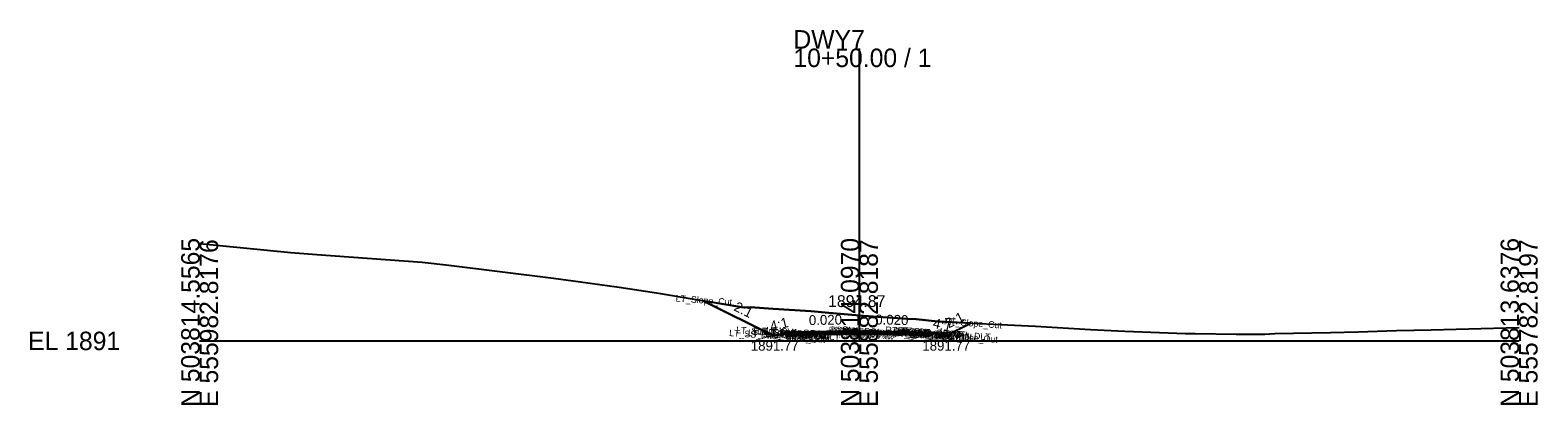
# Model space of a CAD drawing. Extents: x -26 to 1503, y -10 to 1052.
# Drawn here: x -25.7 to 202.8, y 490.3 to 547.1 of the extents above; entities that cross this region are included whole.
import ezdxf

# ---------------------------------------------------------------- set-up
doc = ezdxf.new("R2010")
doc.units = 0
for name, color, linetype in [('Default', 7, 'Continuous'), ('Exist Cross Section Cell', 7, 'Continuous'), ('Exist XS Center Line Elevation Label', 7, 'Continuous'), ('Exist XS Ground Line', 7, 'Continuous'), ('Prop CMT Pvmt Course 1', 7, 'Continuous'), ('Prop CMT Pvmt Course 2', 7, 'Continuous'), ('Prop CMT Pvmt Surface', 7, 'Continuous'), ('Prop CMT Shld Paved Course 1', 7, 'Continuous'), ('Prop CMT Shld Paved Course 2', 7, 'Continuous'), ('Prop CMT Slope Grass', 7, 'Continuous'), ('Prop CMT Subgrade Earthwork', 7, 'Continuous'), ('Prop XS Ditch Standard Text', 7, 'Continuous'), ('Prop XS Earthwork Shape', 7, 'Continuous'), ('Prop XS SE Text', 7, 'Continuous'), ('Prop XS Side Slope Text', 7, 'Continuous'), ('Typical Text Asphalt at Bridge Approach CELL', 7, 'Continuous')]:
    doc.layers.add(name, color=color, linetype=linetype)

msp = doc.modelspace()

# ---------------------------------------------------------------- linework, layer by layer
at = {"layer": 'Exist Cross Section Cell'}
for p, q in [((100, 500), (100, 544.31)), ((0, 500), (100, 500)), ((100, 500), (200, 500))]:
    msp.add_line(p, q, dxfattribs=at)
at = {"layer": 'Exist XS Ground Line'}
for p, q in [((0, 514.77), (13.84, 513.38)), ((13.84, 513.38), (17.75, 513.1)), ((17.75, 513.1), (33.75, 511.94)), ((33.75, 511.94), (37.75, 511.48)), ((37.75, 511.48), (53.66, 509.51)), ((53.66, 509.51), (57.75, 508.93)), ((57.75, 508.93), (63.59, 508.15)), ((63.59, 508.15), (69.27, 507.31)), ((69.27, 507.31), (81.58, 505.2)), ((81.58, 505.2), (82.11, 505.11)), ((82.11, 505.11), (82.77, 505.08)), ((82.77, 505.08), (83.42, 505.11)), ((83.42, 505.11), (86.91, 504.86)), ((86.91, 504.86), (92.65, 504.5)), ((92.65, 504.5), (94.81, 504.33)), ((94.81, 504.33), (100, 503.87)), ((100, 503.87), (100.58, 503.82)), ((100.58, 503.82), (107.27, 503.36)), ((107.27, 503.36), (108.59, 503.29)), ((108.59, 503.29), (111.9, 502.96)), ((111.9, 502.96), (126.71, 502.22)), ((126.71, 502.22), (135.04, 501.72)), ((135.04, 501.72), (140.23, 501.46)), ((140.23, 501.46), (149.43, 501.1)), ((149.43, 501.1), (150.9, 501.1)), ((150.9, 501.1), (157.12, 501.04)), ((157.12, 501.04), (161.46, 501.01)), ((161.46, 501.01), (162.96, 501.1)), ((162.96, 501.1), (171.41, 501.28)), ((171.41, 501.28), (175.59, 501.37)), ((175.59, 501.37), (181.4, 501.6)), ((181.4, 501.6), (186.65, 501.69)), ((186.65, 501.69), (198.05, 501.98)), ((198.05, 501.98), (200, 502.02))]:
    msp.add_line(p, q, dxfattribs=at)
at = {"layer": 'Prop CMT Pvmt Course 1'}
for points in [[(100, 501.55), (90, 501.35)], [(90, 501.35), (90, 501.1)], [(90, 501.1), (100, 501.3)], [(100, 501.3), (100, 501.55)], [(100, 501.55), (110, 501.35)], [(100, 501.3), (100, 501.55)], [(110, 501.1), (100, 501.3)], [(110, 501.35), (110, 501.1)]]:
    msp.add_lwpolyline(points, dxfattribs=at)
msp.add_lwpolyline([(100, 501.3), (100, 501.42), (100, 501.42), (100, 501.3)], close=True, dxfattribs=at)
msp.add_lwpolyline([(100, 501.3), (100, 501.42), (100, 501.42), (100, 501.3)], close=True, dxfattribs=at)
at = {"layer": 'Prop CMT Pvmt Course 2'}
for points in [[(100, 501.3), (90, 501.1)], [(90, 501.1), (90, 500.85)], [(90, 500.85), (100, 501.05)], [(100, 501.05), (100, 501.3)], [(100, 501.05), (100, 501.3)], [(100, 501.3), (110, 501.1)], [(110, 500.85), (100, 501.05)], [(110, 501.1), (110, 500.85)]]:
    msp.add_lwpolyline(points, dxfattribs=at)
at = {"layer": 'Prop CMT Pvmt Surface'}
for points in [[(100, 501.55), (90, 501.35)], [(100, 501.55), (110, 501.35)]]:
    msp.add_lwpolyline(points, dxfattribs=at)
at = {"layer": 'Prop CMT Shld Paved Course 1'}
for points in [[(90, 501.35), (89.74, 501.09)], [(89.74, 501.09), (90, 501.1)], [(90, 501.1), (90, 501.35)], [(110, 501.35), (110.26, 501.09)], [(110, 501.1), (110, 501.35)], [(110.26, 501.09), (110, 501.1)]]:
    msp.add_lwpolyline(points, dxfattribs=at)
at = {"layer": 'Prop CMT Shld Paved Course 2'}
for points in [[(90, 501.1), (89.74, 501.09), (89.24, 501.08), (89, 500.84)], [(89, 500.84), (90, 500.85)], [(90, 500.85), (90, 501.1)], [(110, 501.1), (110.26, 501.09), (110.76, 501.08), (111, 500.84)], [(110, 500.85), (110, 501.1)], [(111, 500.84), (110, 500.85)]]:
    msp.add_lwpolyline(points, dxfattribs=at)
at = {"layer": 'Prop CMT Slope Grass'}
for points in [[(90, 501.35), (89, 501.27), (87, 500.77), (76.33, 506.1)], [(110, 501.35), (111, 501.27), (113, 500.77), (116.89, 502.71)]]:
    msp.add_lwpolyline(points, dxfattribs=at)
at = {"layer": 'Prop CMT Subgrade Earthwork'}
for points in [[(90, 500.85), (89, 500.84), (88.66, 501.18)], [(100, 501.05), (90, 500.85)], [(100, 501.05), (110, 500.85)], [(110, 500.85), (111, 500.84), (111.34, 501.18)]]:
    msp.add_lwpolyline(points, dxfattribs=at)
at = {"layer": 'Prop XS Earthwork Shape'}
for points in [[(111, 501.27), (111.34, 501.18), (113, 500.77), (116.89, 502.71), (111.9, 502.96), (108.59, 503.29), (107.27, 503.36), (100.58, 503.82), (100, 503.87), (94.81, 504.33), (92.65, 504.5), (86.91, 504.86), (83.42, 505.11), (82.77, 505.08), (82.11, 505.11), (81.58, 505.2), (76.33, 506.1), (87, 500.77), (88.66, 501.18), (89, 501.27), (90, 501.35), (100, 501.55), (110, 501.35)], [(100, 501.05), (90, 500.85), (89, 500.84), (88.66, 501.18), (89, 501.27), (90, 501.35), (100, 501.55), (110, 501.35), (111, 501.27), (111.34, 501.18), (111, 500.84), (110, 500.85)]]:
    msp.add_lwpolyline(points, close=True, dxfattribs=at)

# ---------------------------------------------------------------- texts
at = {"layer": 'Default'}
msp.add_text('-', height=0.0001, dxfattribs=at).set_placement((0, 500))
at = {"layer": 'Exist Cross Section Cell'}
for s, p in [('DWY7', (90, 544.31)), ('10+50.00 / 1', (90, 541.51)), ('EL 1891', (-26, 498.6))]:
    msp.add_text(s, height=2.8, dxfattribs=at).set_placement(p)
for s, p in [('N 503814.5565', (0, 490)), ('E 555982.8176', (2.8, 490)), ('N 503814.0970', (100, 490)), ('E 555882.8187', (102.8, 490)), ('N 503813.6376', (200, 490)), ('E 555782.8197', (202.8, 490))]:
    msp.add_text(s, height=2.8, rotation=90, dxfattribs=at).set_placement(p)
at = {"layer": 'Exist XS Center Line Elevation Label'}
msp.add_text('1894.87', height=1.8, dxfattribs=at).set_placement((95.25, 505.13))
at = {"layer": 'Prop XS Ditch Standard Text'}
for p in [(83.54, 498.52), (109.54, 498.52)]:
    msp.add_text('1891.77', height=1.5, dxfattribs=at).set_placement(p)
at = {"layer": 'Prop XS SE Text'}
for rotation, p in [(1.1458, (92.36, 502.39)), (358.8542, (102.4, 502.5))]:
    msp.add_text('0.020', height=1.5, rotation=rotation, dxfattribs=at).set_placement(p)
at = {"layer": 'Prop XS Side Slope Text'}
for s, rotation, p in [('2:1', 333.4349, (80.85, 504.68)), ('4:1', 14.0362, (86.66, 501.46)), ('4:1', 345.9638, (111.03, 502.03)), ('2:1', 26.5651, (113.55, 501.88))]:
    msp.add_text(s, height=1.5, rotation=rotation, dxfattribs=at).set_placement(p)
at = {"layer": 'Typical Text Asphalt at Bridge Approach CELL'}
for s, p in [('LT_Slope_Cut', (72.13, 505.97)), ('RT_Slope_Cut', (112.81, 502.49)), ('LT_SS_Ditch_Base_Out', (80.24, 500.74)), ('LT_Sub_Trench_Out_DLT', (81.29, 501.19)), ('LT_Sub_Trench_Out', (83.09, 500.75)), ('LT_PS2_Shelf_Out', (83.88, 500.95)), ('LT_GS_OS_CTL', (84.44, 501.08)), ('LT_PS2_OEOP', (85.51, 500.89)), ('LT_PV2_OEOT', (85.72, 500.89)), ('LT_Sub_OEOT', (85.74, 500.64)), ('LT_PV1_OEOT', (85.84, 501.14)), ('RT_PV2_OEEOP', (95.31, 501.12)), ('RT_Sub_OEEOP', (95.33, 500.87)), ('LT_PV2_OEEOP', (95.37, 501.12)), ('LT_Sub_OEEOP', (95.39, 500.87)), ('RT_PV1_OEEOP', (95.43, 501.24)), ('LT_PV1_OEEOP', (95.49, 501.24)), ('RT_PV2_IEEOP', (95.69, 501.1)), ('LT_PV2_IEEOP', (95.75, 501.09)), ('RT_PV1_IEEOP', (95.81, 501.21)), ('LT_PV1_IEEOP', (95.87, 501.21)), ('PV2_PGL', (97.32, 500.98)), ('PV1_PGL', (97.44, 501.22)), ('RT_Sub_Trench_Out_DLT', (103.92, 501.2)), ('RT_Sub_Trench_Out', (105.03, 500.75)), ('RT_PS2_Shelf_Out', (105.33, 500.96)), ('RT_PV2_OEOT', (105.66, 500.9)), ('RT_Sub_OEOT', (105.69, 500.65)), ('RT_PV1_OEOT', (105.78, 501.14)), ('RT_PS2_OEOP', (105.96, 500.89)), ('RT_SS_Ditch_Base_Out', (106.18, 500.74)), ('RT_GS_OS_CTL', (106.38, 501.09))]:
    msp.add_text(s, height=1, rotation=356, dxfattribs=at).set_placement(p)

doc.saveas('drawing.dxf')
